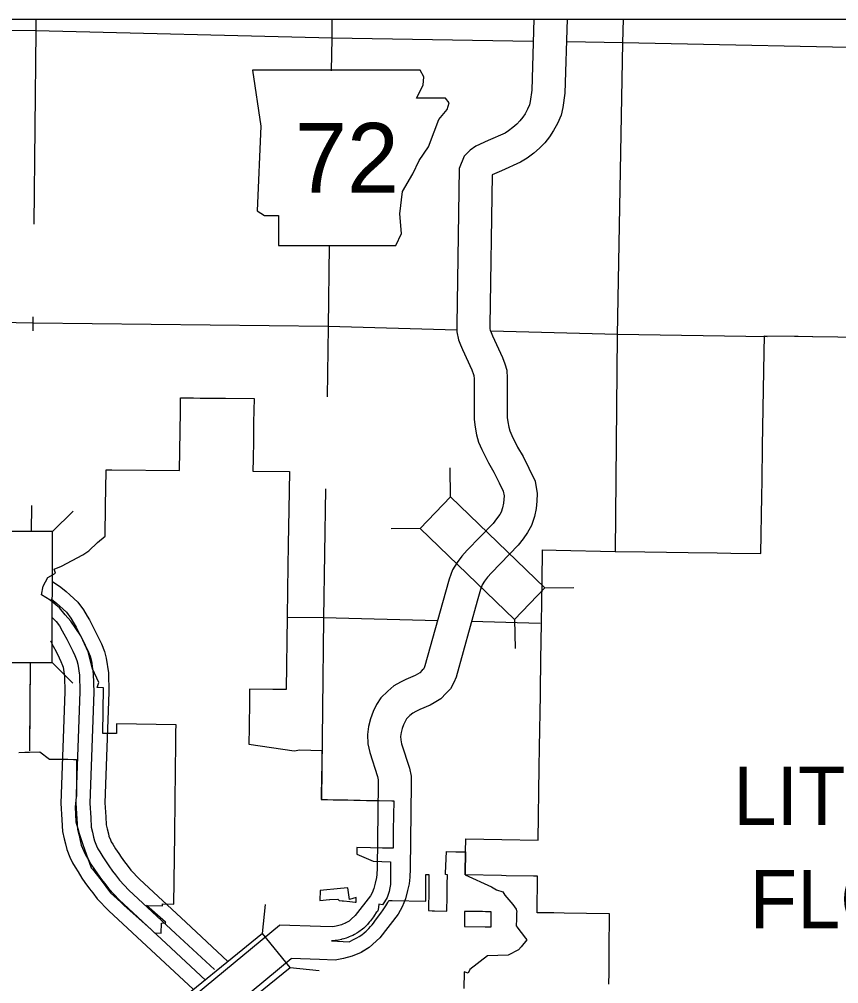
# Model space of a CAD drawing. Extents: x 309389.3 to 309420.2, y 336441.4 to 336461.2.
# Drawn here: x 309391.343 to 309392.47, y 336458.524 to 336459.85 of the extents above; entities that cross this region are included whole.
import ezdxf

# ---------------------------------------------------------------- set-up
doc = ezdxf.new("R2010")
doc.units = 0
for name, color, linetype in [('Level 24', 7, 'Continuous'), ('Level 37', 7, 'Continuous'), ('Level 4', 7, 'Continuous'), ('Level 62', 7, 'Continuous'), ('R_Contours', 7, 'Continuous'), ('R_Erosion', 7, 'Continuous'), ('R_MOT', 7, 'Continuous')]:
    doc.layers.add(name, color=color, linetype=linetype)

msp = doc.modelspace()

# ---------------------------------------------------------------- linework, layer by layer
at = {"layer": 'Level 24'}
for points in [[(309392.0512, 336459.8498), (309392.0482, 336459.7523), (309392.046, 336459.7369), (309392.0449, 336459.7322), (309392.0424, 336459.7263), (309392.0391, 336459.72), (309392.0359, 336459.7152), (309392.0318, 336459.7101), (309392.0274, 336459.7055), (309392.0223, 336459.7011), (309392.016, 336459.6963), (309392.0114, 336459.6934), (309391.988, 336459.683), (309391.9711, 336459.6755), (309391.9635, 336459.6699), (309391.9551, 336459.6616), (309391.9484, 336459.6445)], [(309392.0966, 336459.8498), (309392.0935, 336459.7484), (309392.0907, 336459.7287), (309392.0884, 336459.7182), (309392.0835, 336459.7067), (309392.0782, 336459.6968), (309392.0726, 336459.6882), (309392.0659, 336459.6801), (309392.0587, 336459.6725), (309392.0509, 336459.6658), (309392.042, 336459.6589), (309392.0328, 336459.6532), (309392.0065, 336459.6415), (309391.9937, 336459.6358)], [(309391.9484, 336459.6445), (309391.9452, 336459.4296), (309391.9451, 336459.4202), (309391.9472, 336459.4094), (309391.9502, 336459.4021), (309391.9528, 336459.396), (309391.9659, 336459.3679), (309391.9681, 336459.3617), (309391.9687, 336459.36), (309391.9688, 336459.3557), (309391.9689, 336459.2997), (309391.9702, 336459.2892), (309391.9723, 336459.2784), (309391.9751, 336459.2687), (309391.9796, 336459.2584), (309391.9886, 336459.2402), (309391.9962, 336459.2271), (309392.0034, 336459.2128), (309392.0089, 336459.2013), (309392.01, 336459.1948), (309392.0099, 336459.1899), (309392.0094, 336459.1846), (309392.0078, 336459.1782), (309392.006, 336459.1721), (309392.0043, 336459.1692), (309391.9998, 336459.163), (309391.9949, 336459.1568), (309391.9594, 336459.12), (309391.9519, 336459.1118), (309391.9456, 336459.103), (309391.9392, 336459.0929), (309391.9345, 336459.0804), (309391.9294, 336459.0623), (309391.9013, 336458.9611), (309391.9, 336458.9582), (309391.8992, 336458.9566), (309391.8976, 336458.955), (309391.8944, 336458.9516), (309391.8912, 336458.9498), (309391.8879, 336458.9479), (309391.8752, 336458.9423), (309391.8677, 336458.9387), (309391.8585, 336458.9334), (309391.8501, 336458.9264), (309391.8406, 336458.9169), (309391.8348, 336458.9081), (309391.8301, 336458.8983), (309391.8263, 336458.8883), (309391.8238, 336458.8777), (309391.8223, 336458.8668), (309391.8225, 336458.8538), (309391.8254, 336458.8419), (309391.8358, 336458.8089), (309391.8368, 336458.8042), (309391.837, 336458.7987), (309391.8356, 336458.6831), (309391.8353, 336458.6745), (309391.8347, 336458.67), (309391.8329, 336458.6624), (309391.8312, 336458.6549), (309391.8289, 336458.6493), (309391.8263, 336458.6448), (309391.8055, 336458.6179)], [(309391.9937, 336459.6358), (309391.9906, 336459.4291), (309391.9906, 336459.4245), (309391.991, 336459.4223), (309391.9922, 336459.4194), (309391.9942, 336459.4146), (309392.0081, 336459.3851), (309392.0113, 336459.376), (309392.0139, 336459.3677), (309392.0143, 336459.3565), (309392.0144, 336459.3025), (309392.0151, 336459.2963), (309392.0165, 336459.289), (309392.0179, 336459.2842), (309392.0208, 336459.2776), (309392.0287, 336459.2617), (309392.0362, 336459.2487), (309392.0442, 336459.2328), (309392.0527, 336459.2151), (309392.0555, 336459.198), (309392.0553, 336459.1874), (309392.0544, 336459.1772), (309392.0517, 336459.1663), (309392.048, 336459.1538), (309392.0423, 336459.1442), (309392.0361, 336459.1357), (309392.0293, 336459.127), (309391.9926, 336459.0889), (309391.9873, 336459.0831), (309391.9832, 336459.0775), (309391.9801, 336459.0726), (309391.9778, 336459.0662), (309391.9731, 336459.05), (309391.9442, 336458.9455), (309391.9408, 336458.9381), (309391.9363, 336458.9296), (309391.9304, 336458.9235), (309391.9229, 336458.9156), (309391.9138, 336458.9103), (309391.9084, 336458.9072), (309391.8943, 336458.901), (309391.8889, 336458.8984), (309391.8845, 336458.8959), (309391.8807, 336458.8928), (309391.8761, 336458.8882), (309391.8745, 336458.8857), (309391.8719, 336458.8802), (309391.8698, 336458.875), (309391.8686, 336458.8695), (309391.8678, 336458.864), (309391.8679, 336458.8595), (309391.8692, 336458.8541), (309391.8799, 336458.8204), (309391.8821, 336458.8096), (309391.8824, 336458.7991), (309391.8811, 336458.6821), (309391.8807, 336458.6704), (309391.8794, 336458.6615), (309391.8772, 336458.6521), (309391.8746, 336458.641), (309391.8699, 336458.6296), (309391.8644, 336458.6197), (309391.839, 336458.5873)], [(309391.808, 336458.6206), (309391.797, 336458.6103), (309391.7926, 336458.6077), (309391.7866, 336458.6052), (309391.7791, 336458.6031), (309391.7746, 336458.6023), (309391.7577, 336458.6029), (309391.7014, 336458.6046)], [(309391.808, 336458.6206), (309391.797, 336458.6103), (309391.7926, 336458.6077), (309391.7922, 336458.6075)], [(309391.5368, 336458.4684), (309391.7014, 336458.6046)], [(309391.839, 336458.5873), (309391.8246, 336458.574), (309391.8134, 336458.5671), (309391.8014, 336458.5621), (309391.7893, 336458.5588), (309391.778, 336458.5567), (309391.7562, 336458.5574), (309391.7172, 336458.5586)], [(309391.839, 336458.5873), (309391.8246, 336458.574), (309391.8138, 336458.5673)], [(309391.5725, 336458.4389), (309391.7172, 336458.5586)]]:
    msp.add_lwpolyline(points, dxfattribs=at)
at = {"layer": 'Level 37'}
for p, q in [((309391.9366, 336459.1932), (309391.9359, 336459.2332)), ((309391.3892, 336459.1457), (309391.4176, 336459.1739)), ((309391.3892, 336459.1457), (309391.4176, 336459.1739)), ((309391.8949, 336459.15), (309391.8549, 336459.1493)), ((309392.0661, 336459.0682), (309392.1061, 336459.0689)), ((309392.0244, 336459.025), (309392.0251, 336458.985)), ((309391.3887, 336458.9657), (309391.4169, 336458.9373)), ((309391.3887, 336458.9657), (309391.4169, 336458.9373)), ((309391.678, 336458.5931), (309391.6821, 336458.6329)), ((309391.7158, 336458.5465), (309391.7556, 336458.5424))]:
    msp.add_line(p, q, dxfattribs=at)
for points in [[(309392.0661, 336459.0682), (309391.9366, 336459.1932), (309391.8949, 336459.15), (309392.0244, 336459.025)], [(309391.3887, 336458.9657), (309391.3892, 336459.1457), (309391.3292, 336459.1458), (309391.3287, 336458.9658)], [(309391.3887, 336458.9657), (309391.3892, 336459.1457), (309391.3292, 336459.1458), (309391.3287, 336458.9658)], [(309391.576, 336458.4331), (309391.7158, 336458.5465), (309391.678, 336458.5931), (309391.5382, 336458.4797)]]:
    msp.add_lwpolyline(points, close=True, dxfattribs=at)
at = {"layer": 'Level 4'}
for points in [[(309390.4604, 336459.846), (309390.6118, 336459.843), (309390.9661, 336459.8382), (309391.3663, 336459.8343), (309391.7738, 336459.8244), (309392.0498, 336459.8199)], [(309391.3664, 336459.8498), (309391.3662, 336459.8338), (309391.3635, 336459.5682)], [(309391.7734, 336459.8498), (309391.773, 336459.8236), (309391.7725, 336459.7791)], [(309392.1737, 336459.8498), (309392.1731, 336459.8175), (309392.1658, 336459.4155), (309392.1626, 336459.1184)], [(309392.0962, 336459.8191), (309392.1734, 336459.8178), (309392.5728, 336459.8096), (309392.727, 336459.8075)], [(309391.7696, 336459.5387), (309391.7683, 336459.4269), (309391.7667, 336459.331)], [(309391.3622, 336459.4408), (309391.3621, 336459.4321), (309391.362, 336459.4217)], [(309391.9449, 336459.4225), (309391.7684, 336459.4275), (309391.3626, 336459.4321), (309391.1056, 336459.4371)], [(309392.3718, 336459.4131), (309392.166, 336459.4164), (309391.992, 336459.4212)], [(309391.7646, 336459.2044), (309391.7616, 336459.0266), (309391.7588, 336458.7775)], [(309391.3601, 336459.1813), (309391.3598, 336459.1455)], [(309391.7116, 336459.0282), (309391.7619, 336459.0277), (309391.9189, 336459.0235)], [(309391.9652, 336459.0223), (309392.0595, 336459.0198)], [(309391.3584, 336458.9646), (309391.3577, 336458.8443)], [(309391.3584, 336458.9646), (309391.3577, 336458.8503)]]:
    msp.add_lwpolyline(points, dxfattribs=at)
at = {"layer": 'Level 62'}
for points in [[(309392.1542, 336458.5237), (309392.1544, 336458.5396), (309392.1546, 336458.5702), (309392.1546, 336458.5705), (309392.155, 336458.62), (309392.1236, 336458.6206), (309392.0927, 336458.6211), (309392.0786, 336458.6214), (309392.0554, 336458.6218), (309392.0562, 336458.6718), (309392.0549, 336458.6718), (309392.0505, 336458.6719), (309392.0131, 336458.6726), (309392.0064, 336458.6727), (309391.9565, 336458.6736), (309391.9566, 336458.6755), (309391.957, 336458.7053), (309391.9573, 336458.7235), (309392.0071, 336458.7226), (309392.057, 336458.7216), (309392.0585, 336458.8214), (309392.0589, 336458.8489), (309392.0601, 336458.9212), (309392.0602, 336458.9269), (309392.0608, 336458.9695), (309392.0616, 336459.0199), (309392.0616, 336459.021), (309392.062, 336459.0477), (309392.0624, 336459.0771), (309392.063, 336459.1207), (309392.0818, 336459.1203), (309392.1628, 336459.1184), (309392.2036, 336459.1178), (309392.263, 336459.1169), (309392.3031, 336459.1163), (309392.3217, 336459.116), (309392.3631, 336459.1154), (309392.3644, 336459.1943), (309392.3648, 336459.2152), (309392.3655, 336459.263), (309392.3664, 336459.315), (309392.3677, 336459.3921), (309392.368, 336459.4148), (309392.4093, 336459.4143), (309392.4145, 336459.4143), (309392.4344, 336459.4139), (309392.4348, 336459.4139), (309392.4688, 336459.4135), (309392.5162, 336459.4128)], [(309391.3577, 336458.8425), (309391.3719, 336458.8427), (309391.3851, 336458.8329), (309391.41, 336458.8326), (309391.4181, 336458.8324), (309391.4222, 336458.8324), (309391.422, 336458.7821), (309391.4218, 336458.7804), (309391.4203, 336458.7671), (309391.4213, 336458.7466), (309391.425, 336458.7345), (309391.426, 336458.7307), (309391.4307, 336458.7153), (309391.4421, 336458.6833), (309391.4441, 336458.6818), (309391.4492, 336458.6753), (309391.456, 336458.6666), (309391.4562, 336458.6663), (309391.4689, 336458.6493), (309391.4831, 336458.6362), (309391.4874, 336458.6323), (309391.5247, 336458.5988), (309391.5296, 336458.5939), (309391.5384, 336458.5937), (309391.5389, 336458.6076), (309391.545, 336458.6079), (309391.5445, 336458.6088), (309391.5183, 336458.6317), (309391.5198, 336458.6317), (309391.5405, 336458.6313), (309391.5405, 336458.6338), (309391.5561, 336458.6335), (309391.5572, 336458.7292), (309391.5573, 336458.7307), (309391.5573, 336458.7329), (309391.5574, 336458.7448), (309391.5575, 336458.7502), (309391.5576, 336458.7556), (309391.5576, 336458.7611), (309391.5577, 336458.7665), (309391.5577, 336458.7719), (309391.5578, 336458.7773), (309391.5579, 336458.7827), (309391.5579, 336458.7881), (309391.558, 336458.7936), (309391.5581, 336458.7989), (309391.5581, 336458.8043), (309391.5582, 336458.8098), (309391.5583, 336458.817), (309391.5583, 336458.8208), (309391.5584, 336458.8305), (309391.5585, 336458.8406), (309391.5586, 336458.8486), (309391.5587, 336458.8556), (309391.5588, 336458.8625), (309391.5589, 336458.8703), (309391.559, 336458.8802), (309391.4773, 336458.8812), (309391.4772, 336458.8679), (309391.4584, 336458.8681), (309391.4591, 336458.931), (309391.4521, 336458.9311), (309391.4504, 336458.9311), (309391.4526, 336458.9382), (309391.4441, 336458.957), (309391.4383, 336458.9804), (309391.4282, 336459.0025), (309391.4145, 336459.0224), (309391.4066, 336459.0313), (309391.3986, 336459.041), (309391.3861, 336459.0513), (309391.374, 336459.0589), (309391.3761, 336459.0708), (309391.3826, 336459.0824), (309391.3933, 336459.0885), (309391.3916, 336459.0941), (309391.4014, 336459.098), (309391.4306, 336459.1136), (309391.4389, 336459.119), (309391.4511, 336459.1308), (309391.4617, 336459.1391), (309391.4621, 336459.1808), (309391.4627, 336459.2293), (309391.4627, 336459.2306), (309391.4697, 336459.2305), (309391.4706, 336459.2304), (309391.5637, 336459.2296), (309391.5649, 336459.3107), (309391.5649, 336459.3136), (309391.5652, 336459.3294), (309391.5832, 336459.3293), (309391.5923, 336459.3292), (309391.627, 336459.3288), (309391.6663, 336459.3285), (309391.6657, 336459.2957), (309391.6653, 336459.2703), (309391.6649, 336459.2457), (309391.6646, 336459.2286), (309391.7151, 336459.2281), (309391.7142, 336459.1754)], [(309391.7142, 336459.1754), (309391.7133, 336459.1283), (309391.7122, 336459.0661), (309391.7122, 336459.064), (309391.7116, 336459.0284), (309391.7103, 336458.9284), (309391.6922, 336458.9286), (309391.6601, 336458.929), (309391.6599, 336458.9158), (309391.6594, 336458.8736), (309391.6591, 336458.8562), (309391.6591, 336458.8535), (309391.7212, 336458.8442), (309391.7292, 336458.8457), (309391.7596, 336458.8446), (309391.7595, 336458.8338), (309391.7593, 336458.8276), (309391.7587, 336458.784), (309391.7587, 336458.7835), (309391.7587, 336458.7831), (309391.7586, 336458.7775), (309391.7671, 336458.7773), (309391.775, 336458.7771), (309391.7763, 336458.7771), (309391.7831, 336458.777), (309391.7866, 336458.7769), (309391.7925, 336458.7768), (309391.795, 336458.7768), (309391.8033, 336458.7766), (309391.809, 336458.7765), (309391.8121, 336458.7764), (309391.8211, 336458.7762), (309391.8295, 336458.7761), (309391.8382, 336458.7759), (309391.8559, 336458.7756), (309391.8583, 336458.7755), (309391.8577, 336458.735), (309391.8576, 336458.7255), (309391.8575, 336458.7209), (309391.8574, 336458.7103), (309391.8553, 336458.7104), (309391.8541, 336458.7104), (309391.8427, 336458.7106), (309391.8262, 336458.711), (309391.8075, 336458.7113), (309391.8074, 336458.7023), (309391.83, 336458.6926), (309391.854, 336458.6918), (309391.8539, 336458.6754), (309391.8538, 336458.6712), (309391.8537, 336458.6636), (309391.8538, 336458.6605), (309391.8531, 336458.6561), (309391.8521, 336458.6509), (309391.8493, 336458.6427), (309391.8456, 336458.6369), (309391.843, 336458.6327), (309391.8379, 336458.6334), (309391.8368, 336458.6258), (309391.8366, 336458.6248), (309391.8358, 336458.6236), (309391.8343, 336458.6219), (309391.8319, 336458.6186), (309391.8303, 336458.6159), (309391.8264, 336458.6107), (309391.8247, 336458.6086), (309391.8221, 336458.6056), (309391.8205, 336458.6039), (309391.8187, 336458.6021), (309391.8171, 336458.6007), (309391.8154, 336458.5992), (309391.8136, 336458.5978), (309391.8122, 336458.5967), (309391.8105, 336458.5956), (309391.8077, 336458.5937), (309391.8043, 336458.5917), (309391.8021, 336458.5906), (309391.7995, 336458.5894), (309391.7972, 336458.5884), (309391.7952, 336458.5876), (309391.793, 336458.5869), (309391.7897, 336458.5859), (309391.787, 336458.5852), (309391.7863, 336458.5849), (309391.7825, 336458.5841), (309391.7776, 336458.5834), (309391.7727, 336458.5831), (309391.7969, 336458.5819), (309391.804, 336458.5852), (309391.8074, 336458.587), (309391.8107, 336458.589), (309391.8143, 336458.5915), (309391.8175, 336458.594), (309391.8203, 336458.5964), (309391.8242, 336458.6001), (309391.8265, 336458.6026), (309391.8287, 336458.6052), (309391.8303, 336458.6073), (309391.8325, 336458.6103), (309391.8374, 336458.617)], [(309391.3429, 336458.842), (309391.3509, 336458.8424), (309391.3577, 336458.8425)], [(309391.8374, 336458.617), (309391.8404, 336458.6211), (309391.844, 336458.6258), (309391.8474, 336458.6314), (309391.8502, 336458.636), (309391.8516, 336458.6386), (309391.8564, 336458.6385), (309391.9026, 336458.6377), (309391.9026, 336458.6526), (309391.9027, 336458.6745), (309391.9067, 336458.6745), (309391.9064, 336458.6543), (309391.906, 336458.6247), (309391.911, 336458.6245), (309391.9145, 336458.6244), (309391.9314, 336458.6241), (309391.9315, 336458.6308), (309391.9316, 336458.6372), (309391.9317, 336458.6437), (309391.9318, 336458.6501), (309391.9319, 336458.6565), (309391.932, 336458.663), (309391.9321, 336458.6713), (309391.9322, 336458.674), (309391.9294, 336458.6741), (309391.9295, 336458.676), (309391.9308, 336458.7059), (309391.9438, 336458.7056), (309391.957, 336458.7053), (309391.9566, 336458.6755), (309391.9565, 336458.6736), (309391.9926, 336458.6572), (309391.9997, 336458.6532), (309392.0083, 336458.6505), (309392.0113, 336458.646), (309392.0219, 336458.6331), (309392.0265, 336458.6264), (309392.0277, 336458.6223), (309392.027, 336458.6218), (309392.027, 336458.613), (309392.0268, 336458.6035), (309392.028, 336458.602), (309392.0305, 336458.5987), (309392.0366, 336458.5906), (309392.0377, 336458.589), (309392.0412, 336458.5843), (309392.0335, 336458.5748), (309392.0297, 336458.5708), (309392.0158, 336458.5632), (309391.9871, 336458.5624), (309391.9629, 336458.5435), (309391.9607, 336458.5385), (309391.955, 336458.5407), (309391.955, 336458.5366), (309391.955, 336458.5332), (309391.9549, 336458.5244), (309391.9548, 336458.5175)]]:
    msp.add_lwpolyline(points, dxfattribs=at)
for points in [[(309391.8065, 336458.6363), (309391.8068, 336458.6399), (309391.8066, 336458.6426), (309391.7975, 336458.64), (309391.795, 336458.6561), (309391.785, 336458.655), (309391.757, 336458.6521), (309391.7568, 336458.6387), (309391.7699, 336458.6398), (309391.7703, 336458.6398), (309391.7814, 336458.6403), (309391.7833, 336458.6386), (309391.7876, 336458.6381), (309391.7891, 336458.638), (309391.7981, 336458.6371), (309391.8052, 336458.6363)], [(309391.9925, 336458.6024), (309391.9925, 336458.6224), (309391.9925, 336458.623), (309391.9844, 336458.6231), (309391.9806, 336458.6232), (309391.973, 336458.6233), (309391.9666, 336458.6234), (309391.9601, 336458.6236), (309391.9558, 336458.6236), (309391.9556, 336458.6053), (309391.9556, 336458.603), (309391.9842, 336458.6025)]]:
    msp.add_lwpolyline(points, close=True, dxfattribs=at)
at = {"layer": 'R_Contours'}
msp.add_lwpolyline([(309391.6641, 336459.7798), (309391.6756, 336459.7029), (309391.6705, 336459.5863), (309391.6807, 336459.5799), (309391.6999, 336459.5799), (309391.6999, 336459.5389), (309391.8614, 336459.5389), (309391.8691, 336459.5555), (309391.8666, 336459.5824), (309391.8704, 336459.6132), (309391.8845, 336459.6375), (309391.8935, 336459.6555), (309391.9063, 336459.6747), (309391.914, 336459.6952), (309391.9204, 336459.7119), (309391.9319, 336459.726), (309391.9345, 336459.7349), (309391.9294, 336459.7414), (309391.8896, 336459.7414), (309391.8986, 336459.7593), (309391.8999, 336459.7708), (309391.8946, 336459.7797)], close=True, dxfattribs=at)
at = {"layer": 'R_Erosion'}
for points in [[(309391.3896, 336459.0765), (309391.392, 336459.075), (309391.4004, 336459.0694), (309391.4078, 336459.0632), (309391.413, 336459.0589), (309391.4238, 336459.0487), (309391.4318, 336459.038), (309391.4369, 336459.0293), (309391.4398, 336459.0243), (309391.4439, 336459.016), (309391.4479, 336459.0089), (309391.4529, 336458.9986), (309391.4565, 336458.9912), (309391.4605, 336458.9809), (309391.4631, 336458.9717), (309391.4659, 336458.9516), (309391.4667, 336458.925), (309391.4612, 336458.7727), (309391.4624, 336458.7534), (309391.4631, 336458.7424), (309391.4644, 336458.7369), (309391.466, 336458.7302), (309391.4667, 336458.7269), (309391.4687, 336458.722), (309391.4699, 336458.7193), (309391.472, 336458.7161), (309391.4758, 336458.7096), (309391.4801, 336458.703), (309391.4836, 336458.6979), (309391.488, 336458.6915), (309391.492, 336458.6869), (309391.497, 336458.6801), (309391.5089, 336458.6678), (309391.5726, 336458.6087), (309391.6303, 336458.5549)], [(309391.3872, 336459.0531), (309391.3879, 336459.0526), (309391.3945, 336459.0472), (309391.3991, 336459.0433), (309391.4082, 336459.0348), (309391.4144, 336459.0265), (309391.4189, 336459.0188), (309391.4215, 336459.0143), (309391.4255, 336459.0064), (309391.4294, 336458.9993), (309391.4342, 336458.9895), (309391.4373, 336458.9829), (309391.4407, 336458.9742), (309391.4427, 336458.9673), (309391.4451, 336458.9499), (309391.4458, 336458.9251), (309391.4404, 336458.7725), (309391.4416, 336458.7521), (309391.4425, 336458.7394), (309391.4441, 336458.7323), (309391.4457, 336458.7255), (309391.4468, 336458.7206), (309391.4496, 336458.7138), (309391.4516, 336458.7094), (309391.4542, 336458.7052), (309391.4581, 336458.6987), (309391.4627, 336458.6915), (309391.4665, 336458.6861), (309391.4715, 336458.6788), (309391.4758, 336458.6738), (309391.4811, 336458.6667), (309391.4943, 336458.6529), (309391.5584, 336458.5934), (309391.612, 336458.5436)], [(309391.3872, 336459.0531), (309391.3879, 336459.0526), (309391.3945, 336459.0472), (309391.3991, 336459.0433), (309391.4082, 336459.0348), (309391.4144, 336459.0265), (309391.4189, 336459.0188), (309391.4215, 336459.0143), (309391.4255, 336459.0064), (309391.4294, 336458.9993), (309391.4342, 336458.9895), (309391.4373, 336458.9829), (309391.4407, 336458.9742), (309391.4427, 336458.9673), (309391.4451, 336458.9499), (309391.4458, 336458.9251), (309391.4404, 336458.7725), (309391.4416, 336458.7521), (309391.4425, 336458.7394), (309391.4441, 336458.7323), (309391.4457, 336458.7255), (309391.4468, 336458.7206), (309391.4496, 336458.7138), (309391.4516, 336458.7094), (309391.4542, 336458.7052), (309391.4581, 336458.6987), (309391.4627, 336458.6915), (309391.4665, 336458.6861), (309391.4715, 336458.6788), (309391.4758, 336458.6738), (309391.4811, 336458.6667), (309391.4943, 336458.6529), (309391.5584, 336458.5934), (309391.612, 336458.5436)], [(309391.388, 336459.0278), (309391.394, 336459.0221), (309391.3986, 336459.016), (309391.4025, 336459.0092), (309391.4049, 336459.0053), (309391.4087, 336458.9976), (309391.4126, 336458.9905), (309391.4171, 336458.9813), (309391.42, 336458.9753), (309391.4228, 336458.9682), (309391.4241, 336458.9634), (309391.4262, 336458.9483), (309391.4269, 336458.9252), (309391.4214, 336458.7723), (309391.4227, 336458.7509), (309391.4237, 336458.7366), (309391.4256, 336458.728), (309391.4272, 336458.7212), (309391.4287, 336458.7148), (309391.4322, 336458.7063), (309391.4349, 336458.7004), (309391.4381, 336458.6953), (309391.442, 336458.6887), (309391.4469, 336458.681), (309391.4509, 336458.6753), (309391.4564, 336458.6672), (309391.461, 336458.662), (309391.4666, 336458.6544), (309391.481, 336458.6394), (309391.5455, 336458.5796), (309391.5997, 336458.5291)], [(309391.388, 336459.0278), (309391.394, 336459.0221), (309391.3986, 336459.016), (309391.4025, 336459.0092), (309391.4049, 336459.0053), (309391.4087, 336458.9976), (309391.4126, 336458.9905), (309391.4171, 336458.9813), (309391.42, 336458.9753), (309391.4228, 336458.9682), (309391.4241, 336458.9634), (309391.4262, 336458.9483), (309391.4269, 336458.9252), (309391.4214, 336458.7723), (309391.4227, 336458.7509), (309391.4237, 336458.7366), (309391.4256, 336458.728), (309391.4272, 336458.7212), (309391.4287, 336458.7148), (309391.4322, 336458.7063), (309391.4349, 336458.7004), (309391.4381, 336458.6953), (309391.442, 336458.6887), (309391.4469, 336458.681), (309391.4509, 336458.6753), (309391.4564, 336458.6672), (309391.461, 336458.662), (309391.4666, 336458.6544), (309391.481, 336458.6394), (309391.5455, 336458.5796), (309391.5997, 336458.5291)], [(309391.3865, 336458.9954), (309391.3865, 336458.9954), (309391.3902, 336458.9879), (309391.3941, 336458.9809), (309391.3984, 336458.9722), (309391.4008, 336458.967), (309391.403, 336458.9615), (309391.4037, 336458.9591), (309391.4055, 336458.9466), (309391.406, 336458.9253), (309391.4006, 336458.7721), (309391.4019, 336458.7495), (309391.403, 336458.7336), (309391.4053, 336458.7233), (309391.4069, 336458.7164), (309391.4087, 336458.7085), (309391.413, 336458.698), (309391.4165, 336458.6904), (309391.4203, 336458.6843), (309391.4243, 336458.6778), (309391.4296, 336458.6694), (309391.4337, 336458.6635), (309391.4399, 336458.6545), (309391.4447, 336458.6489), (309391.4506, 336458.6409), (309391.4664, 336458.6245), (309391.5313, 336458.5643), (309391.5826, 336458.5166)]]:
    msp.add_lwpolyline(points, dxfattribs=at)
at = {"layer": 'R_MOT'}
msp.add_lwpolyline([(309389.3351, 336459.8498), (309394.8545, 336459.8498), (309394.8545, 336455.3696), (309389.3351, 336455.3696)], close=True, dxfattribs=at)

# ---------------------------------------------------------------- texts
at = {"layer": 'Level 62'}
for s, p in [('LITTLE', (309392.3251, 336458.7425)), ('FLOCK', (309392.3477, 336458.6004))]:
    msp.add_text(s, height=0.08, dxfattribs=at).set_placement(p)
at = {"layer": 'R_Contours'}
msp.add_text('72', height=0.096, dxfattribs=at).set_placement((309391.7226, 336459.6113))

doc.saveas('drawing.dxf')
